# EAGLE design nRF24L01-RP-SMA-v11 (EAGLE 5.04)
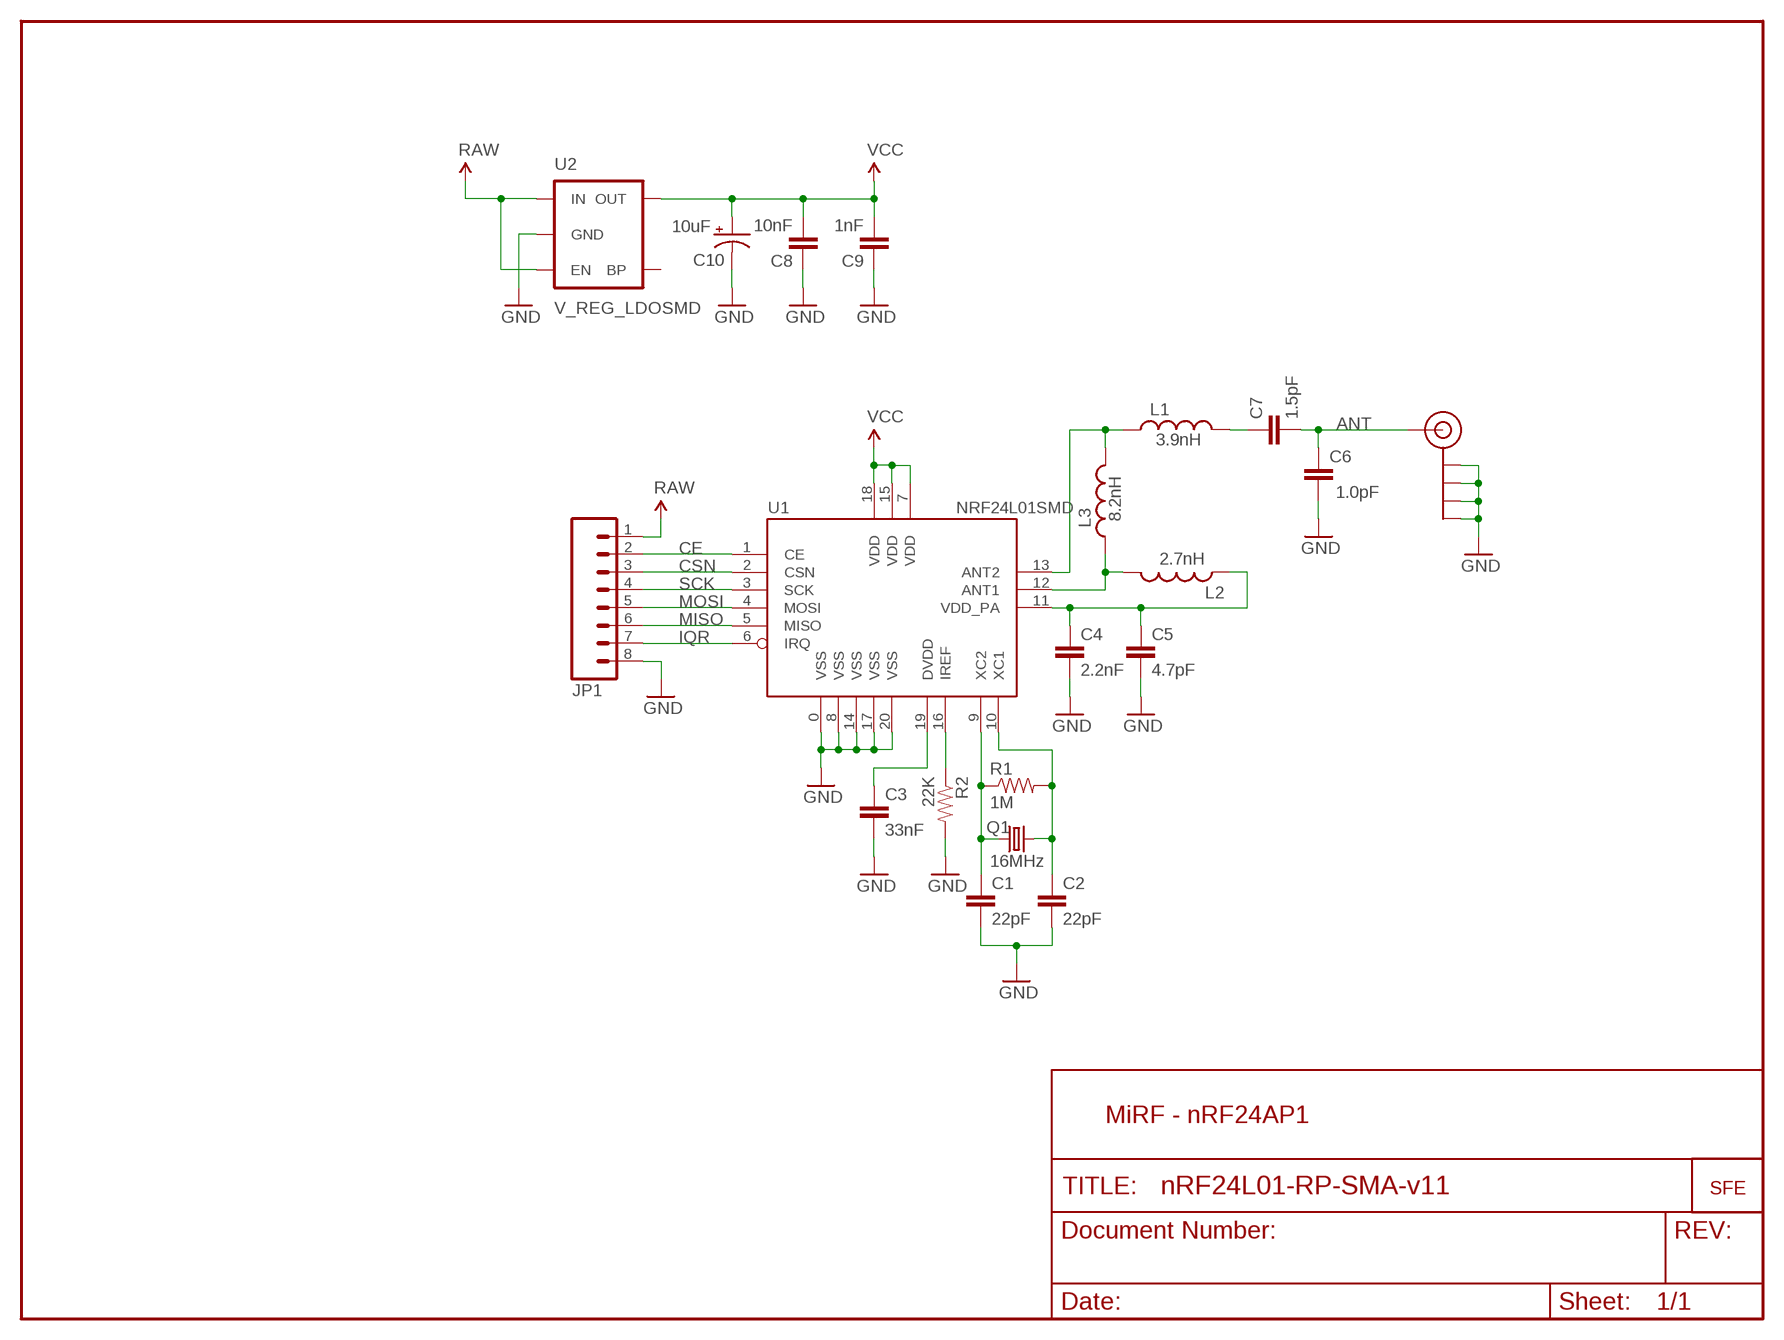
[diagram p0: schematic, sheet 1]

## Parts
C1  22pF  CAP0402  [C0402]
C2  22pF  CAP0402  [C0402]
C3  33nF  CAP0402  [C0402]
C4  2.2nF  CAP0402  [C0402]
C5  4.7pF  CAP0402  [C0402]
C6  1.0pF  CAP0402  [C0402]
C7  1.5pF  CAP0402  [C0402]
C8  10nF  CAP0402  [C0402]
C9  1nF  CAP0402  [C0402]
C10  10uF  CAP_POL1206  [EIA3216]
J$1  SMA_EDGE  [SMA-EDGE]
JP1  M08  [1X08]
L1  3.9nH  INDUCTOR0402  [C0402]
L2  2.7nH  INDUCTOR0402  [C0402]
L3  8.2nH  INDUCTOR0402  [C0402]
Q1  16MHz  CRYSTAL5X3  [CRYSTAL-SMD-5X3]
R1  1M  RESISTOR0402  [C0402]
R2  22K  RESISTOR0402  [C0402]
U1  NRF24L01SMD  [QFN20]
U2  V_REG_LDOSMD  [SOT23-5]
U$5  LOGO-SFENEW  [SFE-NEW-WEBLOGO]

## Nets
ANT: C6.2 C7.2 J$1.SIG(SIGNAL)
CE: JP1.2 U1.1(CE)
CSN: JP1.3 U1.2(CSN)
GND: C1.2 C2.2 C3.2 C4.2 C5.2 C6.1 C8.1 C9.1 C10.C(-) J$1.GND@0(GND) J$1.GND@1(GND) J$1.GND@2(GND) J$1.GND@3(GND) JP1.8 R2.2 U1.0(VSS) U1.8(VSS) U1.14(VSS) U1.17(VSS) U1.20(VSS) U2.2(GND)
IQR: JP1.7 U1.6(IRQ)
MISO: JP1.6 U1.5(MISO)
MOSI: JP1.5 U1.4(MOSI)
N$1: C1.1 Q1.1 R1.1 U1.9(XC2)
N$2: C2.1 Q1.3 R1.2 U1.10(XC1)
N$3: L2.2 L3.1 U1.12(ANT1)
N$4: R2.1 U1.16(IREF)
N$5: C3.1 U1.19(DVDD)
N$6: L1.1 L3.2 U1.13(ANT2)
N$7: C4.1 C5.1 L2.1 U1.11(VDD_PA)
N$9: C7.1 L1.2
RAW: JP1.1 U2.1(IN) U2.3(EN)
SCK: JP1.4 U1.3(SCK)
VCC: C8.2 C9.2 C10.A(+) U1.7(VDD) U1.15(VDD) U1.18(VDD) U2.5(OUT)
Unconnected: U2.4(BP)

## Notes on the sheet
- MiRF - nRF24AP1

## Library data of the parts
C1-C9 = SparkFun:CAP: Capacitor
C10 = SparkFun:CAP_POL: Capacitor Polarized
J$1 = SparkFun:SMA_EDGE: SMA Antenna Connector End launch SMA connector. The paste layer has been removed so that the connector can be hand soldered onto the board after reflow.
JP1 = SparkFun:M08: Header 8 Standard 8-pin 0.1" header. Use with straight break away headers (SKU : PRT-00116), right angle break away headers (PRT-00553), swiss pins (PRT-00743), machine pins (PRT-00117), and female headers (PRT-00115).
L1-L3 = SparkFun:INDUCTOR: Inductors
Q1 = SparkFun:CRYSTAL: Crystals
R1 R2 = SparkFun:RESISTOR: Resistor
U1 = SparkFun:NRF24L01: 2.4GHz Low Power Transceiver This is the very popular, low cost, very low power RF transceiver from Nordic Semiconductor. Simple SPI interface. SKU: COM-00690
U2 = SparkFun:V_REG_LDO: Voltage Regulator LDO Standard 150mA LDO voltage regulator in SOT-23 layout. Micrel part MIC5205. BP (by-pass) pin is used to lower output noise with 470pF cap.
U$5 = SparkFun:LOGO-SFE: Spark Fun Electronics PCB Logo

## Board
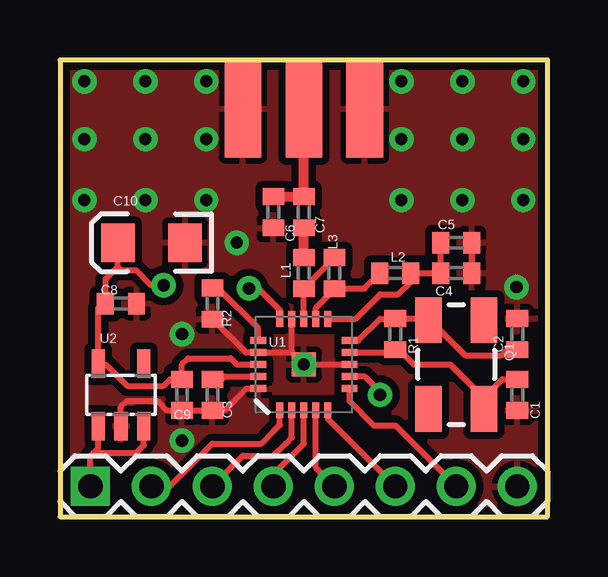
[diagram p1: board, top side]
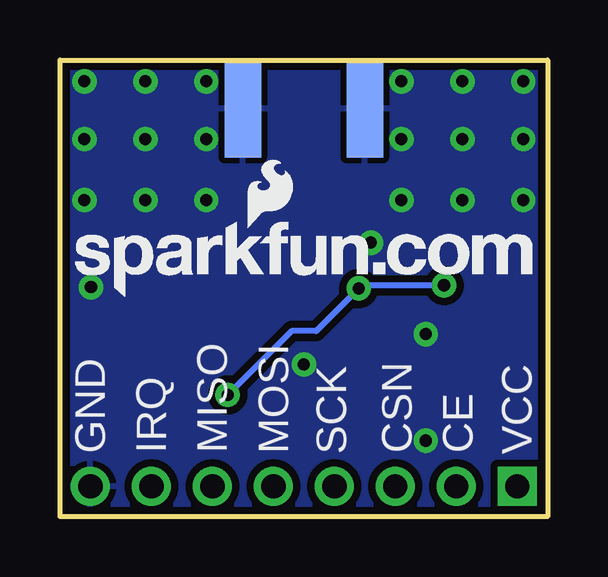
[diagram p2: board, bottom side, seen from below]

Size 20.32 x 19.05 mm. Coordinates in mm from the lower left corner, seen from the top.
Outline: 0,0 20.32,0 20.32,19.05 0,19.05 0,0
Copper layers (1*16): Top 0.035mm / dielectric 1.5mm / Bottom 0.035mm
Design rules "SparkFun *": minimum track width 8mil, minimum drill 20mil, track to track 8mil, track to pad 8mil, pad to pad 7mil, via to via 8mil, smd to smd 8mil, copper to edge 10mil, drill to drill 8mil, minimum pad ring 12mil, minimum via ring 10mil, stop-mask expansion 4mil, vias tented up to drill 25mil, thermal gap 10mil

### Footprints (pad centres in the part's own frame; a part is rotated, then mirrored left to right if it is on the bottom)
C0402 = smd 0.7 x 0.9: 1 -0.65,0; 2 0.65,0
EIA3216 = smd 1.4 x 1.6: A 1.4,0; C -1.4,0
SMA-EDGE = smd 1.524 x 4.064: GND@0 0,0; GND@1 5.08,0; SIG 2.54,0 | smd 1.524 x 4.064 bottom: GND@2 0,0; GND@3 5.08,0
1X08 = drill 1.016 square: 1 0,0 | drill 1.016 round: 2 2.54,0; 3 5.08,0; 4 7.62,0; 5 10.16,0; 6 12.7,0; 7 15.24,0; 8 17.78,0
CRYSTAL-SMD-5X3 = smd 1.9 x 1.1: 1 -1.85,-1.15; 2 1.85,-1.15; 3 1.85,1.15; 4 -1.85,1.15
QFN20 = smd 1 x 1: 0 0,0 | smd 0.65 x 0.3: 1 -1.9,1; 2 -1.9,0.5; 3 -1.9,0; 4 -1.9,-0.5; 5 -1.9,-1; 11 1.9,-1; 12 1.9,-0.5; 13 1.9,0; 14 1.9,0.5; 15 1.9,1 | smd 0.3 x 0.65: 6 -1,-1.9; 7 -0.5,-1.9; 8 0,-1.9; 9 0.5,-1.9; 10 1,-1.9; 16 1,1.9; 17 0.5,1.9; 18 0,1.9; 19 -0.5,1.9; 20 -1,1.9
SOT23-5 = smd 0.55 x 1.2: 1 -0.95,-1.3; 2 0,-1.3; 3 0.95,-1.3; 4 0.95,1.3; 5 -0.95,1.3

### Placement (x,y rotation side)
C1  19.05,5.08 270 top
C2  19.05,7.62 90 top
C3  6.35,5.08 270 top
C4  16.51,10.16 0 top
C5  16.51,11.43 0 top
C6  8.89,12.7 90 top
C7  10.16,12.7 90 top
C8  2.54,8.89 180 top
C9  5.08,5.08 90 top
C10  3.81,11.43 180 top
J$1  12.7,17.02 180 top
JP1  1.27,1.27 0 top
L1  10.16,10.16 90 top
L2  13.97,10.16 180 top
L3  11.43,10.16 90 top
Q1  16.51,6.35 90 top
R1  13.97,7.62 90 top
R2  6.35,8.89 270 top
U1  10.16,6.35 90 top
U2  2.54,5.08 0 top
U$5  19.7,9.18 0 bottom

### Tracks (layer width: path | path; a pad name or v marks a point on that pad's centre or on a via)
ANT
  Top 0.254: J$1.SIG | J$1.SIG | C7.2 10.16,13.34 10.14,13.35
  Top 0.406: C7.2 J$1.SIG | C6.2 10.14,13.35
CE
  Top 0.254: 8.89,3.56 8.38,3.05 6.35,3.05 4.57,1.27 JP1.2 | 8.89,3.56 8.9,3.57 | U1.1 9.16,3.83 8.89,3.56
CSN
  Top 0.254: 9.4,3.05 8.89,2.54 7.62,2.54 JP1.3 | 9.4,3.05 9.4,3.06 | U1.2 9.66,3.31 9.4,3.05
GND  (via drill 0.51)
  Top 0.203: 8.13,6.86 8.12,6.85 U1.17 | 8.13,5.33 8.11,5.35 U1.20
  Top 0.254: 6.35,4.45 6.33,4.43 C9.1 5.08,4.45 4.45,4.45 4.06,4.83 2.79,4.83 2.54,4.57 U2.2 | U1.20 7.76,5.35 6.86,4.45 6.35,4.45 | 6.35,4.45 C3.2 | C4.2 17.14,10.16 17.16,10.18 C5.2 | R2.2 6.35,8.26 7.75,6.85 8.12,6.85 | U1.17 9.66,6.85 | 9.66,6.85 U1.0 | 9.66,6.85 9.67,6.85 9.68,6.86 9.66,6.88 U1.14 | U1.0 U1.8 | U1.0 10.13,6.33
  other vias: 5.08,3.17 5.08,7.62 10.16,6.35 1.02,18.16 3.56,18.16 6.1,18.16 6.1,13.21 14.22,18.16 16.76,18.16 19.3,18.16 16.76,13.21 19.3,13.21 19.02,9.58 1.02,15.75 3.56,15.75 6.1,15.75 14.22,15.75 16.76,15.75 19.3,15.75 1.02,13.21 3.56,13.21 14.22,13.21 7.37,11.43
  pour Bottom (isolate 0.305): 0,0 20.32,0 20.32,19.05 0,19.05
  pour Top (isolate 0.305): 0,0 20.32,0 20.32,19.05 0,19.05
IQR
  Top 0.254: JP1.7 13.97,3.81 13.08,3.81 12.06,4.83 12.06,5.33 U1.6
MISO
  Top 0.254: U1.5 11.16,4.08 JP1.6
MOSI
  Top 0.254: U1.4 10.66,2.04 JP1.5
N$1
  Top 0.203: U1.9 12.2,6.85
  Top 0.254: 12.2,6.85 13.84,6.85 13.97,6.99 R1.1 14.11,6.97 14.73,6.35 16.26,6.35 17.65,4.95 | Q1.1 17.66,4.57 17.65,4.57 17.65,4.95 | C1.1 18.43,5.73 17.65,4.95
N$2
  Top 0.254: U1.10 12.43,7.35 13.34,8.26 13.97,8.26 R1.2 15.35,8.27 15.37,8.26 | C2.1 18.65,6.97 18.41,6.73 16.89,6.73 15.37,8.26 | 15.37,8.26 15.36,8.25 Q1.3
N$3
  Top 0.254: U1.12 10.66,8.7 11.43,9.47 L3.1 12.69,9.51 13.34,10.16 L2.2
N$4
  Top 0.254: U1.16 8.26,7.87 6.6,9.53 6.35,9.53 R2.1
N$5
  Top 0.203: C3.1 6.49,5.48 | 8.13,5.84 8.12,5.85 U1.19
  Top 0.254: 6.49,5.48 6.86,5.84 8.13,5.84
N$6
  Top 0.254: U1.13 L1.1 10.16,9.53 11.43,10.79 L3.2
N$7
  Top 0.254: U1.11 12.31,8.25 13.34,9.27 14.1,9.27 14.61,9.78 14.61,10.16 L2.1 C4.1 | C4.1 15.88,10.16 | C4.1 15.86,10.27 15.88,10.29 15.86,10.3 C5.1
N$9
  Top 0.406: L1.2 C7.1
RAW
  Top 0.254: JP1.1 1.27,2.54 1.4,2.67 | U2.3 3.49,2.98 3.17,2.67 1.4,2.67 | U2.1 1.59,2.86 1.4,2.67
SCK
  Top 0.254: JP1.4 8.89,1.78 10.16,3.05 U1.3
VCC  (via drill 0.51)
  Top 0.203: U1.7 12.18,5.85
  Top 0.254: C9.2 5.09,5.73 | U1.15 9.16,8.62 8.26,9.53 v7.87,9.53 | v13.34,5.08 13.34,5.21 12.69,5.85 U1.7 | 1.89,9 1.91,9.02 | 1.89,9 C8.2 1.91,8.89 1.91,9.91 2.41,10.41 | 1.89,9 1.59,8.7 U2.5 1.62,6.38 1.65,6.35 1.91,6.35 2.79,5.46 4.32,5.46 4.59,5.73 C9.2 | 2.41,10.41 C10.A | v4.32,9.65 3.81,9.65 3.17,10.29 2.54,10.29 2.41,10.41 | U1.18 7.37,6.35 7.11,6.6 5.33,6.6 5.08,6.35 C9.2 | C9.2 5.08,5.71
  Bottom 0.254: v4.32,9.65 7.75,9.65 v7.87,9.53 9.65,7.75 10.67,7.75 v13.34,5.08

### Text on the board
bPlace: VCC | CE | CSN | SCK | MOSI | MISO | IRQ | GND
tValues: RP-SMA | DNP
